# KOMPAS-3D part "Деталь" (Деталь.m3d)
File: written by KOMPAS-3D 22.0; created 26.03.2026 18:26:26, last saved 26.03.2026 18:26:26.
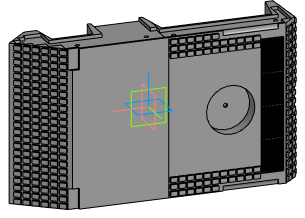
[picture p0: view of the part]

Document properties: Автор: Пользователь Windows; Полное имя файла: F:\Танк\Деталь.m3d

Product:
- Part/product: Деталь

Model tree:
1. Операция без истории:1
2. Операция без истории:2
